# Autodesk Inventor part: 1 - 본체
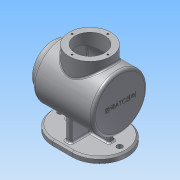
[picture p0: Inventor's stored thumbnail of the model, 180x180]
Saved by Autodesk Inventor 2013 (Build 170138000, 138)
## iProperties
Created: 2016-04
Part Number: 1 - 본체
Material: 알루미늄 6061
Document SubType Name: Modeling
Designer: Administrator
Density: 2.71 g/cm^3
Mass: 928.149 g
Surface Area: 1292.99 cm^2
Volume: 342.491 cm^3
Author: Administrator
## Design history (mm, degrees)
sketch "스케치1"
  geometry: L1 (-17.5, 50)-(17.5, 50); L2 (17.5, -50)-(-17.5, -50); A1 r 50 centre (17.5, 0) between (17.5, -50) and (17.5, 50); A2 r 50 centre (-17.5, 0) between (-17.5, 50) and (-17.5, -50); 2 further points
  constraints: 4 end point, 4 point on circle, 4 tangent, 2 centre point, 2 horizontal alignment, 1 horizontal, 1 midpoint, 1 parallel, 1 vertical alignment
  dimensions: "d0" = 100 distance between parallel lines of L2 L1; "d2" = 135 dimension on A2 A1
extrude "돌출1" new body sketch "스케치1" distance "d3" = 10; taper "d4" = 0 deg
sketch "스케치2"
  geometry: C1 r 50 at (0, 79); 1 further point
  constraints: 1 centre point, 1 vertical alignment
  dimensions: "d5" = 79 distance of point (0, 0) C1.centre; "d6" = 100 diameter of C1
extrude "돌출2" join sketch "스케치2" stored distance "d7" = 110; taper "d8" = 0 deg
sketch "스케치3"
  geometry: L1 (-17.5, 10)-(-67.5, 10) reference; L2 (67.5, 10)-(17.5, 10) reference; L3 (55, 29)-(-55, 29) reference; L4 (-40, 10)-(-36.65, 29); L5 (36.65, 29)-(40, 10); L6 (-36.65, 29)-(36.65, 29); L7 (-40, 10)-(40, 10); 1 further point
  constraints: 8 end point, 4 point on line, 2 collinear
  dimensions: "d9" = 40 horizontal distance of point (0, 0) L4.start; "d10" = 40 horizontal distance of point (0, 0) L5.end; "d11" = 100 deg angle of L5 L2; "d12" = 100 deg angle of L1 L4
extrude "돌출3" join sketch "스케치3" stored distance "d13" = 10; taper "d14" = 0 deg
sketch "스케치4"
  geometry: L1 (50, 10)-(-50, 10) reference; L2 (-40, 49)-(-40, 10); L3 (40, 49)-(40, 10); A1 r 50 centre (0, 79) between (-40, 49) and (40, 49) reference; 1 further point
  constraints: 4 end point, 2 point on circle, 2 point on line, 1 perpendicular, 1 vertical
  dimensions: "d15" = 40 distance from line of L3 point (0, 0); "d16" = 40 horizontal distance of point (0, 0) L2.end
extrude "돌출4" join sketch "스케치4" stored distance "d17" = 10; taper "d18" = 0 deg
sketch "스케치5"
  geometry: C1 r 50 at (0, 0) reference; C2 r 38 at (0, 0); 1 further point
  constraints: 1 centre point, 1 coincident
  dimensions: "d19" = 76 diameter of C2
extrude "돌출5" join sketch "스케치5" distance "d21" = 12; taper "d22" = 0 deg
node "작업 평면1"
sketch "스케치6"
  geometry: C1 r 38 at (0, 0); 1 further point
  constraints: 1 centre point, 1 coincident
  dimensions: "d24" = 76 diameter of C1
extrude "돌출6" join sketch "스케치6" distance "d26" = 40; taper "d27" = 0 deg
sketch "스케치9"
  geometry: L1 (-55, 129)-(-55, 29) reference; L2 (67, 41)-(67, 117) reference; L3 (-55, 79)-(67, 79); L4 (-52, 79)-(-52, 126); L5 (-52, 126)-(52, 126); L6 (52, 126)-(52, 106); L7 (52, 106)-(67, 106); L8 (55, 129)-(-55, 129) reference; L9 (55, 29)-(55, 129) reference; 1 further point
  constraints: 10 end point, 3 perpendicular, 2 midpoint, 2 point on line, 1 parallel
  dimensions: "d28" = 3 distance between parallel lines of L1 L4; "d29" = 3 distance between parallel lines of L8 L5; "d30" = 54 diameter of L7 L3; "d31" = 3 distance between parallel lines of L9 L6
revolve "회전1" sketch "스케치9" stored, may be unused: angle "d32" = 90 deg
hole "구멍1" diameter "d35" = 54; stored, may be unused: countersink angle "d39" = 90 deg, drill point angle "d41" = 0 deg; dims "d33" = 10, "d34" = 10, "d36" = 6, "d37" = 4, "d38" = 2, "d40" = 30
sketch "스케치10"
  geometry: 3 further points
  constraints: 2 horizontal alignment
  dimensions: "d42" = 54 distance of point (0, 0) point (-54, 0); "d43" = 54 distance of point (54, 0) point (0, 0)
hole "구멍2" sketch "스케치10" at (-54, 0), (54, 0) diameter "d44" = 10; stored, may be unused: countersink angle "d48" = 90 deg, drill point angle "d50" = 0 deg; dims "d45" = 6, "d46" = 4, "d47" = 2, "d49" = 10
sketch "스케치11"
  geometry: C1 r 47 at (0, 0) reference; C2 r 27 at (0, 0) reference; A1 r 32.5 centre (0, 0) between (32.5, 0) and (0, 32.5); 3 further points
  constraints: 4 point on circle, 1 centre point, 1 coincident
  dimensions: "d51" = 65 diameter of A1
hole "구멍3" sketch "스케치11" at (32.5, 0), (0, 32.5), (-32.5, 0), (0, -32.5) diameter "d54" = 3.242; stored, may be unused: countersink angle "d58" = 90 deg, drill point angle "d60" = 118 deg; dims "d55" = 8, "d56" = 4, "d57" = 2, "d59" = 10
sketch "스케치12"
  geometry: A1 r 32.5 centre (0, 0) between (0, 32.5) and (32.5, 0); 3 further points
  constraints: 4 point on circle, 2 horizontal alignment, 2 vertical alignment, 1 centre point, 1 coincident
  dimensions: "d61" = 65 diameter of A1
hole "구멍4" sketch "스케치12" at (0, 32.5), (32.5, 0), (0, -32.5), (-32.5, 0) diameter "d63" = 3.242; stored, may be unused: countersink angle "d67" = 90 deg, drill point angle "d69" = 118 deg; dims "d64" = 8, "d65" = 4, "d66" = 2, "d68" = 10
fillet "모깎기1" dims "d70" = 5
fillet "모깎기2" dims "d71" = 3
fillet "모깎기3" dims "d72" = 3
fillet "모깎기4" dims "d73" = 3
chamfer "모따기1" distance "d74" = 3; stored, may be unused: second distance "d75" = 2, angle "d76" = 45 deg
fillet "모깎기5" dims "d77" = 2
chamfer "모따기2" distance "d78" = 2; stored, may be unused: second distance "d79" = 2, angle "d80" = 45 deg
sketch "스케치13"
  geometry: L1 (-4.48, -28.667)-(-4.48, 29.403); L2 (-4.48, 29.403)-(3.925, 29.403); L3 (3.925, 29.403)-(3.925, -28.667); L4 (3.925, -28.667)-(-4.48, -28.667); C1 r 45 at (0, 0) reference; 2 further points
  constraints: 1 coincident, 2 other
feature "엠보싱1" sketch "스케치13" dims "d0" = 100, "d2" = 135, "d9" = 40, "d10" = 40, "d11" = 100 deg, "d12" = 100 deg, "d81" = 0.5, "d82" = 0
node "솔리드1"
node "투영된 루프1"
node "투영된 루프3"
other parameters: "d23" = 144
